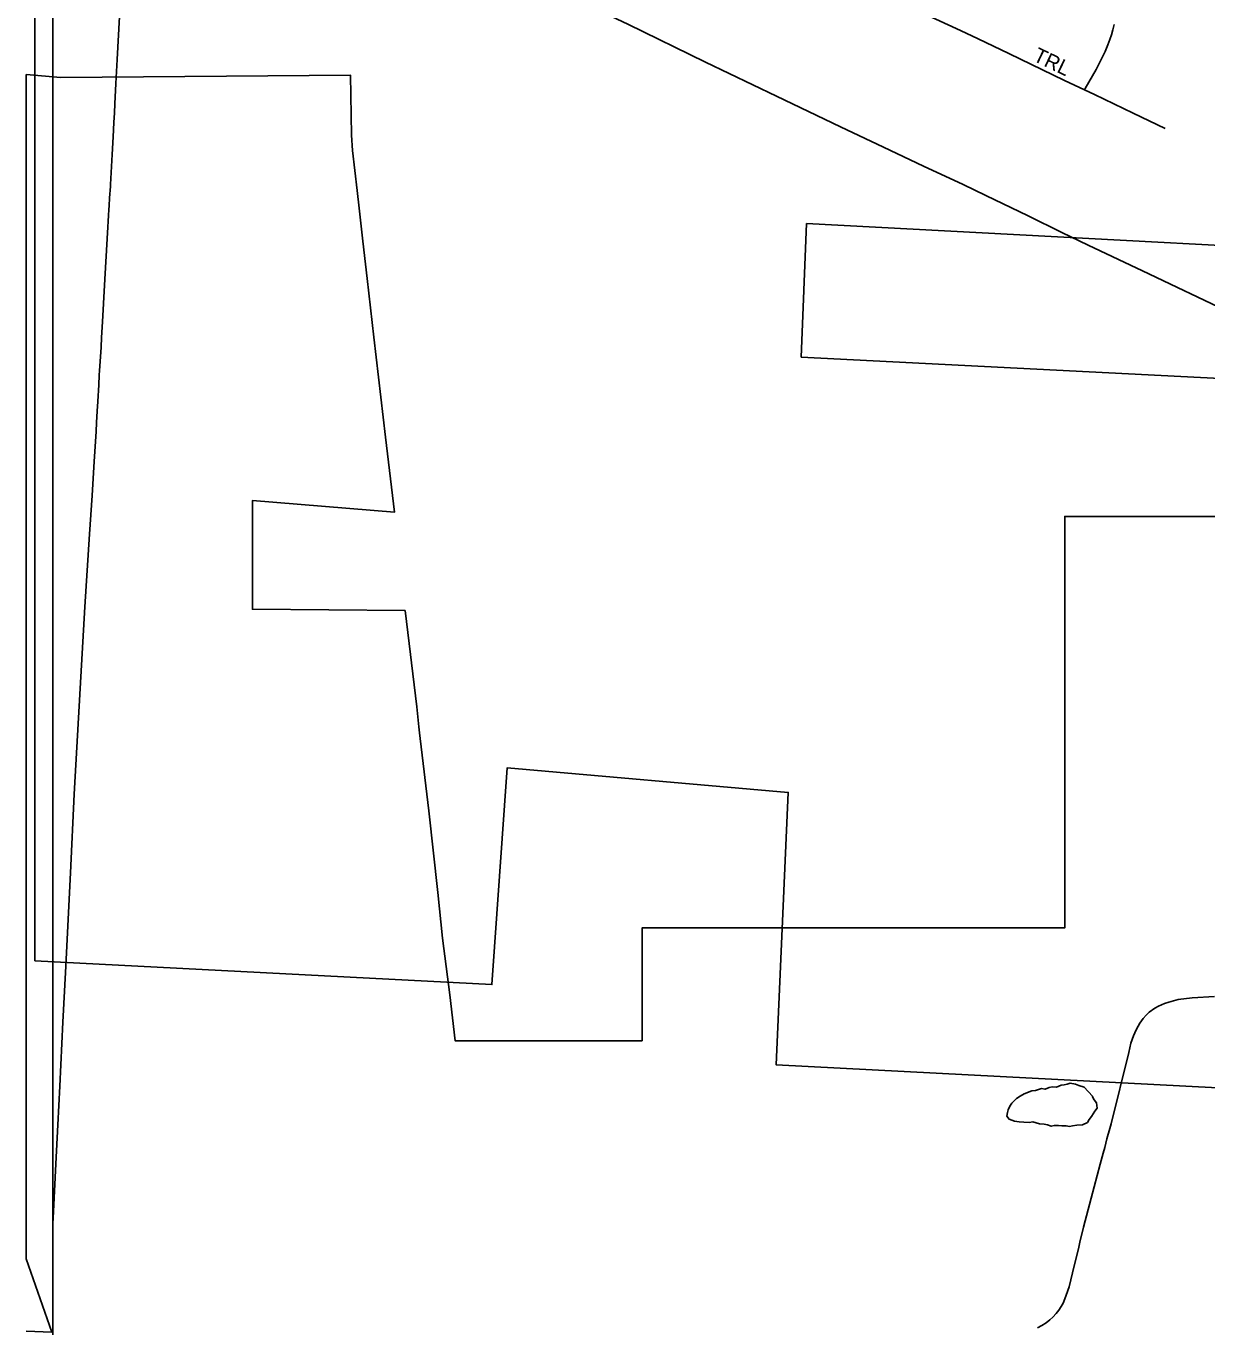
# Model space of a CAD drawing. Extents: x -5.4 to 49.9, y 13.2 to 48.4.
# Drawn here: x 26.26 to 27.015, y 41.82 to 42.652 of the extents above; entities that cross this region are included whole.
import ezdxf

# ---------------------------------------------------------------- set-up
doc = ezdxf.new("R2010")
doc.units = 0
for name, color, linetype in [('GM_X_Corporation', 7, 'Continuous'), ('GM_X_County_Road', 7, 'Continuous'), ('GM_X_Minor_Lake', 7, 'Continuous'), ('GM_X_Township', 7, 'Continuous'), ('GM_X_Township_Road', 7, 'Continuous'), ('GM_X_Township_Subdivision', 7, 'Continuous'), ('GM_X_Township_Subdivision_Text', 7, 'Continuous')]:
    doc.layers.add(name, color=color, linetype=linetype)

msp = doc.modelspace()

# ---------------------------------------------------------------- linework, layer by layer
at = {"layer": 'GM_X_Corporation'}
for p, q in [((26.26551, 43.78252), (26.26551, 42.05419)), ((26.25991, 42.62093), (26.25991, 41.86368))]:
    msp.add_line(p, q, dxfattribs=at)
for points in [[(27.24409, 42.33848), (26.92422, 42.33848), (26.92422, 42.07536), (26.65397, 42.07538), (26.65397, 42.00322), (26.53429, 42.00323), (26.53106, 42.03252), (26.5263, 42.06885), (26.52336, 42.09795), (26.51755, 42.15014), (26.51205, 42.19635), (26.51163, 42.19998), (26.51118, 42.20388), (26.50984, 42.21667), (26.50232, 42.27818), (26.4047, 42.27904), (26.40475, 42.34857), (26.4955, 42.34113), (26.48978, 42.38917), (26.48247, 42.45298), (26.47808, 42.49059), (26.47704, 42.49961), (26.47532, 42.51435), (26.47294, 42.53558), (26.47161, 42.54685), (26.46878, 42.57249), (26.46801, 42.5821), (26.46754, 42.62048), (26.28223, 42.61909), (26.25991, 42.62093)], [(26.75914, 42.52582), (27.23255, 42.50052), (27.2539, 42.41497), (26.75577, 42.44027), (26.75914, 42.52582)], [(26.26551, 42.05419), (26.55791, 42.03913), (26.56758, 42.17762), (26.74738, 42.16192), (26.7396, 41.98783), (27.3866, 41.95403), (27.38866, 42.07279), (27.47945, 42.06805), (27.42847, 42.1818), (27.4542, 42.1938), (27.55288, 41.98056), (27.67472, 41.75149)], [(26.25991, 41.86368), (26.2765, 41.81681), (26.25991, 41.81758)]]:
    msp.add_lwpolyline(points, dxfattribs=at)
at = {"layer": 'GM_X_County_Road'}
for points in [[(26.59236, 42.67796), (26.59986, 42.6744), (26.64477, 42.65311), (26.6945, 42.62894), (26.73983, 42.6071), (26.78075, 42.58757), (26.80831, 42.57462), (26.83401, 42.56232), (26.85936, 42.55058), (26.87388, 42.54353), (26.90078, 42.53072), (26.9225, 42.51997), (26.93923, 42.51181), (26.97405, 42.49539), (27.03132, 42.46825), (27.06275, 42.45329), (27.11662, 42.42769), (27.1357, 42.41862), (27.15695, 42.4083), (27.18263, 42.39579), (27.20393, 42.38562), (27.21459, 42.38058), (27.23308, 42.37173), (27.23815, 42.36925)], [(26.90693, 41.81961), (26.90962, 41.8212), (26.91231, 41.82289), (26.91465, 41.82466), (26.9167, 41.82656), (26.91868, 41.82878), (26.92039, 41.83095), (26.92198, 41.83331), (26.92321, 41.83545), (26.92437, 41.83817), (26.92524, 41.84057), (26.927, 41.84595), (26.93039, 41.85926), (26.933, 41.87014), (26.934, 41.87436), (26.93628, 41.88402), (26.94119, 41.90262), (26.94698, 41.92421), (26.94888, 41.93141), (26.94984, 41.935), (26.95128, 41.94039), (26.95306, 41.94698), (26.95387, 41.94997), (26.96518, 41.99576), (26.96664, 42.00173), (26.96817, 42.00636), (26.96988, 42.01024), (26.97119, 42.01249), (26.9724, 42.01436), (26.97453, 42.01746), (26.97632, 42.0195), (26.97835, 42.02137), (26.98194, 42.02405), (26.98414, 42.02536), (26.98813, 42.02707), (26.99081, 42.02796), (26.99675, 42.02959), (27.00571, 42.03065), (27.02008, 42.03157)]]:
    msp.add_lwpolyline(points, dxfattribs=at)
at = {"layer": 'GM_X_Minor_Lake'}
msp.add_lwpolyline([(26.942, 41.96766), (26.93674, 41.97342), (26.93334, 41.97459), (26.93107, 41.97538), (26.92766, 41.97617), (26.92576, 41.97543), (26.92386, 41.97507), (26.92196, 41.97471), (26.91891, 41.9736), (26.91625, 41.97363), (26.91435, 41.97327), (26.91168, 41.97216), (26.90941, 41.97256), (26.9056, 41.97146), (26.90332, 41.97111), (26.89837, 41.96926), (26.8957, 41.96777), (26.89341, 41.96627), (26.89034, 41.96326), (26.88918, 41.96138), (26.88802, 41.95911), (26.88762, 41.95722), (26.88721, 41.95494), (26.88871, 41.95303), (26.89212, 41.95185), (26.89515, 41.95144), (26.89818, 41.95103), (26.9016, 41.951), (26.90388, 41.95135), (26.90804, 41.95017), (26.91107, 41.94976), (26.91334, 41.94935), (26.91561, 41.94857), (26.91751, 41.94893), (26.92017, 41.9489), (26.92244, 41.94888), (26.9251, 41.94885), (26.92737, 41.94845), (26.92928, 41.94881), (26.93193, 41.94916), (26.93573, 41.9495), (26.93879, 41.95099), (26.93994, 41.95287), (26.94148, 41.95476), (26.94342, 41.95815), (26.94495, 41.96004), (26.94461, 41.96346), (26.94311, 41.96538), (26.94199, 41.96729), (26.94199, 41.96729), (26.942, 41.96766)], dxfattribs=at)
at = {"layer": 'GM_X_Township'}
msp.add_line((26.2771, 45.17828), (26.2771, 40.9761), dxfattribs=at)
at = {"layer": 'GM_X_Township_Road'}
msp.add_lwpolyline([(26.2771, 41.88613), (26.27751, 41.89412), (26.27903, 41.92452), (26.28025, 41.94934), (26.28153, 41.97416), (26.28352, 42.0151), (26.28518, 42.04674), (26.28839, 42.11064), (26.29081, 42.1609), (26.2945, 42.22851), (26.29757, 42.2806), (26.30052, 42.32709), (26.30215, 42.35188), (26.30358, 42.37358), (26.30468, 42.3928), (26.30498, 42.39838), (26.30537, 42.40582), (26.30577, 42.41201), (26.3064, 42.42254), (26.30674, 42.42874), (26.30694, 42.43183), (26.30749, 42.44051), (26.30787, 42.4467), (26.30825, 42.45289), (26.30878, 42.46281), (26.30938, 42.47459), (26.31001, 42.48638), (26.31203, 42.51978), (26.31268, 42.53092), (26.31293, 42.53463), (26.31309, 42.5371), (26.31339, 42.54204), (26.31385, 42.54947), (26.31391, 42.55071), (26.31495, 42.56991), (26.3156, 42.58106), (26.31613, 42.59036), (26.31648, 42.59656), (26.3167, 42.60214), (26.31739, 42.61515), (26.31821, 42.63066), (26.31961, 42.65817)], dxfattribs=at)
at = {"layer": 'GM_X_Township_Subdivision'}
for points in [[(26.73404, 42.70811), (26.74654, 42.70177), (26.76507, 42.69304), (26.78927, 42.68167), (26.81669, 42.66842), (26.83398, 42.66002), (26.85763, 42.64911), (26.86881, 42.64375), (26.88844, 42.63433), (26.92416, 42.61719), (26.93697, 42.61118)], [(26.93697, 42.61118), (26.9374, 42.61197), (26.94444, 42.62416), (26.94795, 42.63152), (26.95002, 42.63575), (26.95181, 42.64), (26.95306, 42.64332), (26.95415, 42.64642), (26.95504, 42.64957), (26.95595, 42.653)], [(26.93697, 42.61118), (26.94329, 42.60822), (26.96795, 42.5963), (26.98848, 42.58637)]]:
    msp.add_lwpolyline(points, dxfattribs=at)

# ---------------------------------------------------------------- texts
at = {"layer": 'GM_X_Township_Subdivision_Text'}
msp.add_text('TRL', height=0.00947, rotation=334.4471, dxfattribs=at).set_placement((26.90336, 42.63005))

doc.saveas('drawing.dxf')
